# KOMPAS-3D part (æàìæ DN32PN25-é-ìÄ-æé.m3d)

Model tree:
1. Объединить компоненты:1  (labels: СЕНС DN32PN25-В-НО)
2. Эскиз:1
3. Операция выдавливания:1
     Расстояние 1 = 14
4. Фаска:1
     Угол = 45; Длина 1 = 2; Длина 2 = 2

Referenced files in D:\Савин\!СЕНСОР\3D для заказчика\!Новый перечень\СЕНС\6. СЕНС-В-НО\DN32\: СЕНС DN32PN25-В-НО.a3d
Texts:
  СЕНС DN32PN25-В-НО-СВ
  ООО НПП Сенсор
  СЕНС DN32PN25-В-НО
